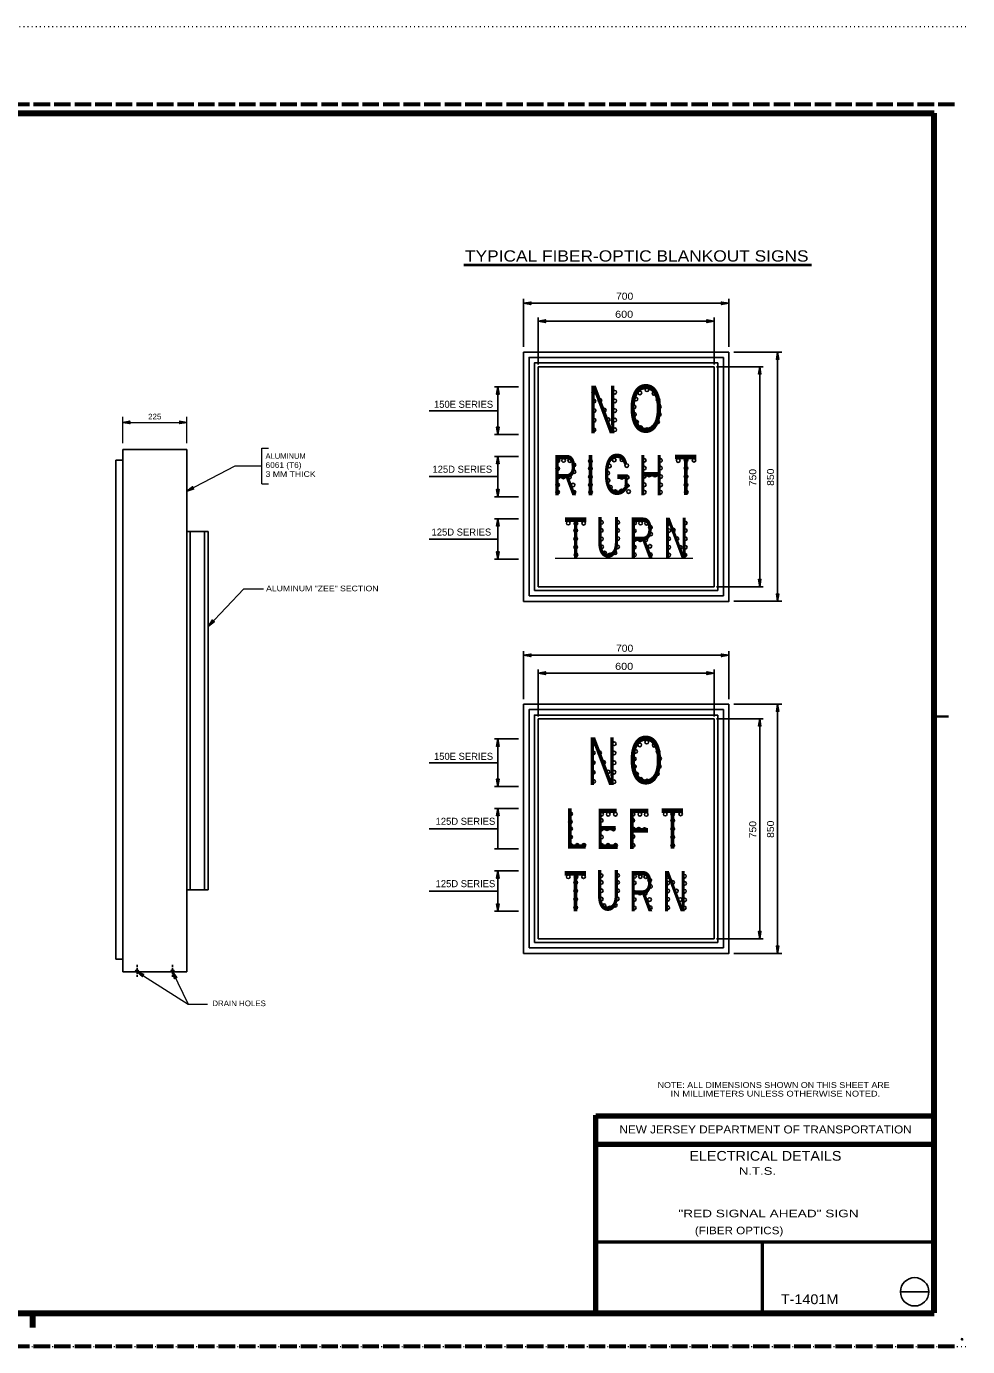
# Model space of a CAD drawing. Extents: x 312583 to 312854, y 144419 to 144597.
# Drawn here: x 312726.5 to 312853.5, y 144418.6 to 144596.8 of the extents above; entities that cross this region are included whole.
import ezdxf
from ezdxf.enums import TextEntityAlignment as Align

# ---------------------------------------------------------------- set-up
doc = ezdxf.new("R2010")
doc.units = 0
doc.header["$LTSCALE"] = 0.37
doc.header["$PDMODE"] = 32
doc.header["$PDSIZE"] = 0.185
doc.linetypes.add('DOTTED', pattern=[1.5, 0.3, -1.2])
doc.linetypes.add('LONG_DASHED', pattern=[7.5, 6, -1.5])
for name, color, linetype, lineweight in [('1', 7, 'Continuous', 25), ('10', 7, 'Continuous', 25), ('2', 7, 'Continuous', 25), ('62', 7, 'DOTTED', 13), ('63', 7, 'LONG_DASHED', 60)]:
    doc.layers.add(name, color=color, linetype=linetype, lineweight=lineweight)

msp = doc.modelspace()

# ---------------------------------------------------------------- linework, layer by layer
at = {"layer": '1', "lineweight": 158}
for p, q in [((312849, 144423.1446), (312849, 144585.0846)), ((312616.5, 144423.0846), (312849, 144423.0846)), ((312727.35, 144421.1646), (312727.35, 144423.0846))]:
    msp.add_line(p, q, dxfattribs=at)
at = {"layer": '1'}
for p, q in [((312793.5601, 144519.1749), (312793.5601, 144552.8349)), ((312793.5601, 144552.8349), (312821.2801, 144552.8349)), ((312795.5401, 144550.8549), (312819.3001, 144550.8549)), ((312795.5401, 144521.1549), (312795.5401, 144550.8549)), ((312819.3001, 144521.1549), (312819.3001, 144550.8549)), ((312819.7911, 144520.6638), (312819.7911, 144551.3538)), ((312820.5356, 144519.9194), (312820.5356, 144552.0983)), ((312738.5204, 144470.8853), (312738.5204, 144538.2293)), ((312738.5204, 144538.2293), (312739.4788, 144538.2293)), ((312739.4788, 144469.191), (312739.4788, 144539.663)), ((312739.4788, 144539.663), (312748.1038, 144539.663)), ((312748.1038, 144469.191), (312748.1038, 144539.663)), ((312748.1038, 144528.623), (312750.9788, 144528.623)), ((312748.5868, 144480.231), (312748.5868, 144528.623)), ((312750.5034, 144480.231), (312750.5034, 144528.623)), ((312750.9788, 144480.231), (312750.9788, 144528.623)), ((312795.0411, 144520.6638), (312819.7911, 144520.6638)), ((312795.5401, 144521.1549), (312819.3001, 144521.1549)), ((312794.3046, 144519.9194), (312820.5356, 144519.9194)), ((312793.5601, 144471.6549), (312793.5601, 144505.3149)), ((312793.5601, 144505.3149), (312821.2801, 144505.3149)), ((312820.5356, 144472.3994), (312820.5356, 144504.5783)), ((312795.5401, 144503.3349), (312819.3001, 144503.3349)), ((312795.5401, 144473.6349), (312795.5401, 144503.3349)), ((312819.3001, 144473.6349), (312819.3001, 144503.3349)), ((312819.7911, 144473.1438), (312819.7911, 144503.8338)), ((312748.1038, 144480.231), (312750.9788, 144480.231)), ((312794.3046, 144472.3994), (312820.5356, 144472.3994)), ((312795.0411, 144473.1438), (312819.7911, 144473.1438)), ((312795.5401, 144473.6349), (312819.3001, 144473.6349)), ((312738.5204, 144470.8853), (312739.4788, 144470.8853)), ((312739.4788, 144469.191), (312748.1038, 144469.191)), ((312741.3954, 144469.8426), (312741.3954, 144470.1033)), ((312741.3954, 144468.8613), (312741.3954, 144469.7276)), ((312741.3954, 144468.501), (312741.3954, 144468.7233)), ((312746.1871, 144469.8426), (312746.1871, 144470.1033)), ((312746.1871, 144468.8613), (312746.1871, 144469.7276)), ((312746.1871, 144468.501), (312746.1871, 144468.7233))]:
    msp.add_line(p, q, dxfattribs=at)
at = {"layer": '1', "lineweight": 13}
msp.add_line((312797.8448, 144525.0278), (312816.4093, 144525.0278), dxfattribs=at)
at = {"layer": '1', "lineweight": 35}
msp.add_line((312849, 144503.6216), (312850.932, 144503.6216), dxfattribs=at)
at = {"layer": '1', "lineweight": 80}
for p, q in [((312803.31, 144423.1446), (312803.31, 144449.8146)), ((312803.31, 144449.7246), (312849, 144449.7246)), ((312803.31, 144445.9146), (312849, 144445.9146))]:
    msp.add_line(p, q, dxfattribs=at)
at = {"layer": '1', "lineweight": 53}
for p, q in [((312849, 144432.6666), (312803.115, 144432.6666)), ((312825.7546, 144432.6666), (312825.7546, 144423.1446))]:
    msp.add_line(p, q, dxfattribs=at)
at = {"layer": '1', "lineweight": 158}
msp.add_lwpolyline([(312616.5, 144423.1446), (312616.5, 144585.0846), (312849, 144585.0846)], dxfattribs=at)
at = {"layer": '1'}
for points in [[(312793.5601, 144519.1749), (312821.2801, 144519.1749), (312821.2801, 144552.8349)], [(312794.3046, 144519.9194), (312794.3046, 144552.0983), (312820.5356, 144552.0983)], [(312795.0411, 144520.6638), (312795.0411, 144551.3538), (312819.7911, 144551.3538)], [(312793.5601, 144471.6549), (312821.2801, 144471.6549), (312821.2801, 144505.3149)], [(312794.3046, 144472.3994), (312794.3046, 144504.5783), (312820.5356, 144504.5783)], [(312795.0411, 144473.1438), (312795.0411, 144503.8338), (312819.7911, 144503.8338)]]:
    msp.add_lwpolyline(points, dxfattribs=at)
for centre in [(312803.0483, 144547.384), (312805.8787, 144547.4048), (312809.2635, 144547.3068), (312810.2159, 144547.7315), (312811.1723, 144547.2355), (312803.0721, 144546.2109), (312803.0879, 144544.9258), (312803.868, 144546.295), (312804.4601, 144544.9971), (312805.8708, 144546.2396), (312805.8708, 144544.9387), (312808.4824, 144545.4317), (312808.725, 144546.4861), (312811.7227, 144546.399), (312811.895, 144545.4515), (312803.08, 144543.6171), (312805.0105, 144543.7002), (312805.8708, 144543.6378), (312808.526, 144544.4001), (312808.8121, 144543.3775), (312811.6514, 144543.4012), (312811.89, 144544.412), (312803.0562, 144542.3251), (312805.8708, 144542.338), (312809.3507, 144542.632), (312810.2001, 144542.3499), (312811.0535, 144542.6637), (312798.2142, 144538.1701), (312798.9606, 144538.1938), (312799.7972, 144538.1691), (312802.588, 144538.1226), (312805.8094, 144538.2542), (312806.842, 144538.2918), (312809.8536, 144538.2077), (312812.0474, 144538.1998), (312814.4403, 144538.1839), (312815.5134, 144538.2156), (312816.5707, 144538.2077), (312798.1825, 144537.1088), (312800.3585, 144537.5998), (312800.3585, 144536.6653), (312802.588, 144537.1326), (312802.588, 144536.0079), (312804.9273, 144536.493), (312805.1491, 144537.4454), (312807.4984, 144537.5038), (312809.8457, 144537.1702), (312809.8615, 144536.0693), (312810.5139, 144536.2336), (312811.296, 144536.2257), (312812.0474, 144537.1623), (312812.0553, 144536.0297), (312815.5134, 144537.1543), (312815.5134, 144536.0297), (312798.1587, 144534.8991), (312798.1983, 144535.9525), (312798.9378, 144535.9624), (312799.7566, 144535.9505), (312800.2565, 144534.8833), (312802.588, 144534.8833), (312804.9808, 144535.4941), (312805.2837, 144534.5813), (312806.841, 144535.9248), (312807.5103, 144534.7991), (312807.5736, 144535.9158), (312809.8694, 144534.913), (312812.0553, 144534.9051), (312815.5134, 144534.9051), (312798.1666, 144533.925), (312800.3585, 144533.9091), (312802.6038, 144533.9091), (312805.9342, 144533.9883), (312806.7668, 144534.0556), (312807.7399, 144533.9913), (312809.8694, 144533.9151), (312812.0395, 144533.8992), (312815.5293, 144533.9309), (312799.5952, 144529.7323), (312800.6288, 144529.7085), (312801.6782, 144529.7165), (312804.0799, 144529.8254), (312806.2886, 144529.8412), (312808.5616, 144529.7501), (312809.3635, 144529.7422), (312810.1684, 144529.7175), (312810.6901, 144529.1482), (312813.2057, 144529.7145), (312815.4015, 144529.7531), (312800.6208, 144528.7423), (312800.6208, 144527.6177), (312804.0482, 144528.7562), (312804.0799, 144527.6157), (312806.2728, 144528.7482), (312806.2886, 144527.6474), (312808.4983, 144528.6888), (312808.5537, 144527.5246), (312809.3249, 144527.487), (312810.0645, 144527.4989), (312810.706, 144528.2612), (312813.1503, 144527.6236), (312813.1582, 144528.7403), (312813.768, 144528.7888), (312814.2561, 144527.6266), (312815.3936, 144528.7314), (312815.4015, 144527.6226), (312800.6208, 144526.493), (312800.6446, 144525.4713), (312804.1116, 144526.5227), (312804.5106, 144525.6961), (312805.2342, 144525.4466), (312805.8946, 144525.7278), (312806.249, 144526.5227), (312808.522, 144526.495), (312808.53, 144525.4733), (312810.6278, 144526.6059), (312810.6901, 144525.4654), (312813.1582, 144525.4377), (312813.1661, 144526.4831), (312814.7105, 144526.4495), (312815.3382, 144525.4367), (312815.4015, 144526.4901), (312802.977, 144498.7305), (312803.0325, 144499.9511), (312803.8205, 144498.7354), (312805.7916, 144498.7116), (312805.7995, 144499.9482), (312808.6933, 144498.9265), (312809.2556, 144499.7947), (312810.2001, 144500.1798), (312811.2039, 144499.7472), (312811.7306, 144498.9106), (312802.985, 144497.4058), (312804.3729, 144497.4454), (312805.7837, 144497.3949), (312808.5062, 144497.9196), (312808.526, 144496.8801), (312811.89, 144496.8999), (312811.9266, 144497.9632), (312802.977, 144496.0971), (312804.9471, 144496.1565), (312805.7758, 144496.1178), (312808.8121, 144495.8575), (312809.3982, 144495.1358), (312811.101, 144495.2229), (312811.6356, 144495.8971), (312803.0087, 144494.8764), (312805.7679, 144494.818), (312810.2318, 144494.917), (312799.912, 144490.4897), (312804.0888, 144490.4511), (312804.9897, 144490.4352), (312805.9589, 144490.4422), (312808.3498, 144490.4669), (312809.2665, 144490.4352), (312810.1248, 144490.4184), (312812.68, 144490.4659), (312813.6898, 144490.458), (312814.7709, 144490.4739), (312799.8962, 144489.4284), (312799.912, 144488.4939), (312804.0611, 144489.6007), (312804.069, 144488.4602), (312804.8343, 144488.479), (312805.7005, 144488.4622), (312808.3062, 144489.6007), (312808.3696, 144488.4444), (312809.1071, 144488.4107), (312809.911, 144488.378), (312813.7057, 144489.6185), (312813.7057, 144488.4939), (312799.912, 144487.3692), (312799.9358, 144486.2446), (312800.8198, 144486.2376), (312801.7039, 144486.2604), (312804.069, 144487.3514), (312804.1007, 144486.2347), (312804.9778, 144486.2268), (312805.9787, 144486.2258), (312808.3379, 144487.4227), (312808.3458, 144486.2426), (312813.7057, 144487.3692), (312813.7057, 144486.2446), (312799.5952, 144481.9985), (312800.6208, 144481.2223), (312800.6525, 144481.9905), (312801.6623, 144482.0143), (312804.0324, 144482.1549), (312804.0482, 144481.2362), (312806.249, 144482.1786), (312806.249, 144481.2362), (312808.4983, 144481.1688), (312808.53, 144482.04), (312809.3239, 144482.0163), (312810.0575, 144482.0153), (312810.603, 144481.5252), (312813.0394, 144481.1728), (312813.079, 144482.044), (312813.6809, 144481.2292), (312815.2748, 144482.0668), (312815.2986, 144481.1005), (312800.6208, 144480.0977), (312800.6208, 144478.973), (312804.0482, 144480.1115), (312804.0482, 144478.9869), (312806.2252, 144479.0106), (312806.2569, 144480.1194), (312808.5141, 144479.8937), (312809.2774, 144479.7927), (312810.0011, 144479.7809), (312810.6901, 144480.6936), (312813.0394, 144480.0957), (312814.2007, 144480.0828), (312815.2827, 144480.0472), (312800.6208, 144477.8484), (312804.4393, 144478.081), (312805.1946, 144477.784), (312805.9342, 144478.1523), (312808.4983, 144478.9196), (312808.4983, 144477.7949), (312810.5723, 144478.9196), (312810.6585, 144477.8108), (312813.0315, 144478.9631), (312813.0315, 144477.8306), (312814.7105, 144478.9295), (312815.259, 144477.7979), (312815.2907, 144478.8829)]:
    msp.add_circle(centre, 0.2475, dxfattribs=at)
for centre in [(312741.3983, 144469.189), (312746.19, 144469.189)]:
    msp.add_arc(centre, 0.2396, 0, 180, dxfattribs=at)
msp.add_point((312852.75, 144419.5846), dxfattribs=at)
at = {"layer": '10'}
msp.add_line((312844.4384, 144425.9659), (312848.2794, 144425.9659), dxfattribs=at)
msp.add_circle((312846.3494, 144425.9805), 1.9159, dxfattribs=at)
at = {"layer": '2', "lineweight": 40}
msp.add_line((312785.4989, 144564.5869), (312832.4133, 144564.5869), dxfattribs=at)
at = {"layer": '2'}
for p, q in [((312793.5601, 144553.516), (312793.5601, 144559.9946)), ((312821.2801, 144559.4164), (312793.5601, 144559.4164)), ((312821.2801, 144553.516), (312821.2801, 144559.9946)), ((312795.5401, 144551.1558), (312795.5401, 144557.4839)), ((312819.3001, 144557.0008), (312795.5401, 144557.0008)), ((312819.3001, 144551.1558), (312819.3001, 144557.4839)), ((312821.9612, 144552.8349), (312828.4319, 144552.8349)), ((312827.8537, 144519.1828), (312827.8537, 144552.8349)), ((312819.6011, 144550.8549), (312825.9212, 144550.8549)), ((312825.446, 144521.1549), (312825.446, 144550.8549)), ((312789.6555, 144548.1225), (312792.8711, 144548.1225)), ((312790.0911, 144541.6994), (312790.0911, 144548.1225)), ((312790.0911, 144544.907), (312780.8327, 144544.907)), ((312789.6555, 144541.6994), (312792.8711, 144541.6994)), ((312789.6555, 144538.7452), (312792.8711, 144538.7452)), ((312790.0911, 144533.2804), (312790.0911, 144538.7452)), ((312790.0911, 144536.0128), (312780.8327, 144536.0128)), ((312807.6102, 144534.7773), (312807.8953, 144534.7773)), ((312789.6555, 144533.2804), (312792.8711, 144533.2804)), ((312789.6555, 144530.3262), (312792.8711, 144530.3262)), ((312790.0911, 144524.8694), (312790.0911, 144530.3262)), ((312790.0911, 144527.5938), (312780.8327, 144527.5938)), ((312789.6555, 144524.8694), (312792.8711, 144524.8694)), ((312819.6011, 144521.1549), (312825.9212, 144521.1549)), ((312821.9612, 144519.1828), (312828.4319, 144519.1828)), ((312793.5601, 144505.996), (312793.5601, 144512.4746)), ((312821.2801, 144511.8964), (312793.5601, 144511.8964)), ((312821.2801, 144505.996), (312821.2801, 144512.4746)), ((312795.5401, 144503.6358), (312795.5401, 144509.9639)), ((312819.3001, 144503.6358), (312819.3001, 144509.9639)), ((312819.3001, 144509.4808), (312795.5401, 144509.4808)), ((312821.9612, 144505.3149), (312828.4319, 144505.3149)), ((312827.8537, 144471.6628), (312827.8537, 144505.3149)), ((312819.6011, 144503.3349), (312825.9212, 144503.3349)), ((312825.446, 144473.6349), (312825.446, 144503.3349)), ((312789.6555, 144500.6025), (312792.8711, 144500.6025)), ((312790.0911, 144497.387), (312780.8327, 144497.387)), ((312789.6555, 144494.1794), (312792.8711, 144494.1794)), ((312789.6555, 144491.2252), (312792.8711, 144491.2252)), ((312790.0911, 144485.7604), (312790.0911, 144491.2252)), ((312790.0911, 144488.4928), (312780.8327, 144488.4928)), ((312789.6555, 144485.7604), (312792.8711, 144485.7604)), ((312789.6555, 144482.8062), (312792.8711, 144482.8062)), ((312790.0911, 144477.3494), (312790.0911, 144482.8062)), ((312790.0911, 144480.0738), (312780.8327, 144480.0738)), ((312789.6555, 144477.3494), (312792.8711, 144477.3494)), ((312819.6011, 144473.6349), (312825.9212, 144473.6349)), ((312821.9612, 144471.6628), (312828.4319, 144471.6628))]:
    msp.add_line(p, q, dxfattribs=at)
at = {"layer": '2', "lineweight": 13}
for p, q in [((312739.4788, 144540.514), (312739.4788, 144544.079)), ((312748.1038, 144540.514), (312748.1038, 144544.079)), ((312739.4788, 144543.3276), (312748.1038, 144543.3276)), ((312758.2391, 144537.4473), (312754.6128, 144537.4473)), ((312758.2391, 144535.0476), (312759.1284, 144535.0476)), ((312751.0554, 144515.8503), (312755.8011, 144520.8873)), ((312755.8011, 144520.8873), (312758.4538, 144520.8873)), ((312741.3954, 144469.191), (312748.2801, 144464.8056)), ((312746.1871, 144469.191), (312748.2801, 144464.8056)), ((312748.2801, 144464.8056), (312750.9251, 144464.8056))]:
    msp.add_line(p, q, dxfattribs=at)
at = {"layer": '2'}
for points in [[(312793.5601, 144559.4164), (312794.558, 144559.2501), (312794.2254, 144559.4164), (312794.558, 144559.5827)], [(312821.2801, 144559.4164), (312820.2822, 144559.5827), (312820.6148, 144559.4164), (312820.2822, 144559.2501)], [(312795.5401, 144557.0008), (312796.538, 144556.8345), (312796.2054, 144557.0008), (312796.538, 144557.1671)], [(312819.3001, 144557.0008), (312818.3022, 144557.1671), (312818.6348, 144557.0008), (312818.3022, 144556.8345)], [(312827.8537, 144552.8349), (312827.6874, 144551.837), (312827.8537, 144552.1696), (312828.02, 144551.837)], [(312825.446, 144550.8549), (312825.2797, 144549.857), (312825.446, 144550.1896), (312825.6123, 144549.857)], [(312790.0911, 144548.1225), (312789.9327, 144547.1246), (312790.0911, 144547.4572), (312790.2654, 144547.1246)], [(312739.4788, 144543.3276), (312740.4448, 144543.1666), (312740.1228, 144543.3276), (312740.4448, 144543.4886)], [(312748.1038, 144543.3276), (312747.1378, 144543.4886), (312747.4598, 144543.3276), (312747.1378, 144543.1666)], [(312790.0911, 144541.6994), (312790.2654, 144542.6973), (312790.0911, 144542.3646), (312789.9327, 144542.6973)], [(312790.0911, 144538.7452), (312789.9327, 144537.7473), (312790.0911, 144538.0799), (312790.2654, 144537.7473)], [(312748.1038, 144534.0663), (312749.0391, 144534.3653), (312748.6788, 144534.3653), (312748.8934, 144534.6566)], [(312790.0911, 144533.2804), (312790.2654, 144534.2783), (312790.0911, 144533.9457), (312789.9327, 144534.2783)], [(312790.0911, 144530.3262), (312789.9327, 144529.3283), (312790.0911, 144529.661), (312790.2654, 144529.3283)], [(312790.0911, 144524.8694), (312790.2654, 144525.8673), (312790.0911, 144525.5346), (312789.9327, 144525.8673)], [(312825.446, 144521.1549), (312825.6123, 144522.1528), (312825.446, 144521.8202), (312825.2797, 144522.1528)], [(312827.8537, 144519.1828), (312828.02, 144520.1807), (312827.8537, 144519.8481), (312827.6874, 144520.1807)], [(312751.0554, 144515.8503), (312751.8298, 144516.4406), (312751.4924, 144516.318), (312751.5998, 144516.663)], [(312793.5601, 144511.8964), (312794.558, 144511.7301), (312794.2254, 144511.8964), (312794.558, 144512.0627)], [(312821.2801, 144511.8964), (312820.2822, 144512.0627), (312820.6148, 144511.8964), (312820.2822, 144511.7301)], [(312795.5401, 144509.4808), (312796.538, 144509.3145), (312796.2054, 144509.4808), (312796.538, 144509.6471)], [(312819.3001, 144509.4808), (312818.3022, 144509.6471), (312818.6348, 144509.4808), (312818.3022, 144509.3145)], [(312827.8537, 144505.3149), (312827.6874, 144504.317), (312827.8537, 144504.6496), (312828.02, 144504.317)], [(312825.446, 144503.3349), (312825.2797, 144502.337), (312825.446, 144502.6696), (312825.6123, 144502.337)], [(312790.0911, 144494.1794), (312790.2654, 144495.1773), (312790.0911, 144494.8446), (312789.9327, 144495.1773)], [(312790.0911, 144491.2252), (312789.9327, 144490.2273), (312790.0911, 144490.5599), (312790.2654, 144490.2273)], [(312790.0911, 144482.8062), (312789.9327, 144481.8083), (312790.0911, 144482.141), (312790.2654, 144481.8083)], [(312790.0911, 144477.3494), (312790.2654, 144478.3473), (312790.0911, 144478.0146), (312789.9327, 144478.3473)], [(312825.446, 144473.6349), (312825.6123, 144474.6328), (312825.446, 144474.3002), (312825.2797, 144474.6328)], [(312827.8537, 144471.6628), (312828.02, 144472.6607), (312827.8537, 144472.3281), (312827.6874, 144472.6607)], [(312741.3954, 144469.191), (312742.1238, 144468.5316), (312741.9398, 144468.846), (312742.3001, 144468.8076)], [(312746.1871, 144469.191), (312746.4631, 144468.248), (312746.4708, 144468.6083), (312746.7544, 144468.386)]]:
    msp.add_lwpolyline(points, close=True, dxfattribs=at)
at = {"layer": '2', "lineweight": 13}
for points in [[(312758.2391, 144535.0476), (312758.2391, 144539.8393), (312759.1284, 144539.8393)], [(312758.2391, 144537.4473), (312754.6128, 144537.4473), (312748.1038, 144534.0663)]]:
    msp.add_lwpolyline(points, dxfattribs=at)
at = {"layer": '2'}
msp.add_lwpolyline([(312790.0911, 144494.1794), (312790.0911, 144500.6025), (312789.9327, 144499.6046), (312790.0911, 144499.9372), (312790.2654, 144499.6046), (312790.0911, 144500.6025)], dxfattribs=at)
at = {"layer": '62'}
for p, q in [((312601.2, 144596.7846), (312853.5, 144596.7846)), ((312601.2, 144418.5846), (312853.5, 144418.5846))]:
    msp.add_line(p, q, dxfattribs=at)
at = {"layer": '63'}
for p, q in [((312851.75, 144586.2246), (312583.526, 144586.2246)), ((312851.75, 144418.5846), (312583.526, 144418.5846))]:
    msp.add_line(p, q, dxfattribs=at)

# ---------------------------------------------------------------- texts
at = {"layer": '1'}
for s, height, width, p in [('N', 6.431, 0.65, (312804.273, 144541.8578)), ('O', 6.431, 0.7, (312810.065, 144541.9924)), ('R', 5.441, 0.65, (312799.1622, 144533.5101)), ('I', 5.441, 0.75, (312802.6053, 144533.4863)), ('G', 5.441, 0.65, (312806.138, 144533.6051)), ('H', 5.441, 0.65, (312810.7655, 144533.4942)), ('T', 5.441, 0.7, (312815.467, 144533.518)), ('T', 5.441, 0.7, (312800.5933, 144525.0594)), ('U', 5.441, 0.65, (312804.9914, 144525.1386)), ('R', 5.441, 0.65, (312809.49, 144525.0594)), ('N', 5.441, 0.65, (312814.1039, 144525.0198)), ('N', 6.431, 0.65, (312804.1859, 144494.3774)), ('O', 6.431, 0.7, (312810.0728, 144494.5358)), ('L', 5.441, 0.75, (312800.6341, 144485.7762)), ('E', 5.441, 0.65, (312804.8763, 144485.7683)), ('F', 5.441, 0.7, (312809.0707, 144485.7683)), ('T', 5.441, 0.7, (312813.6613, 144485.7921)), ('U', 5.441, 0.65, (312804.9598, 144477.4682)), ('R', 5.441, 0.65, (312809.4583, 144477.3414)), ('N', 5.441, 0.65, (312813.977, 144477.3494)), ('T', 5.441, 0.7, (312800.5695, 144477.3335)), ('NEW JERSEY DEPARTMENT OF TRANSPORTATION', 1.08, 1.1, (312826.2285, 144447.3546)), ('ELECTRICAL DETAILS', 1.315, 1.1, (312826.2107, 144443.6759)), ('T-1401M', 1.319, 1.1, (312832.1762, 144424.3176))]:
    msp.add_text(s, height=height, dxfattribs=dict(at, width=width)).set_placement(p, align=Align.CENTER)
for s, width, p in [('NOTE: ALL DIMENSIONS SHOWN ON THIS SHEET ARE', 1.15, (312811.6611, 144453.5054)), ('     IN MILLIMETERS UNLESS OTHERWISE NOTED.', 1.2, (312811.661, 144452.3354))]:
    msp.add_text(s, height=0.78, dxfattribs=dict(at, width=width)).set_placement(p)
at = {"layer": '2'}
for s, height, width, p in [('TYPICAL FIBER-OPTIC BLANKOUT SIGNS', 1.52, 1.15, (312808.847, 144565.0394)), ('700', 0.9504, 1.1, (312807.2075, 144559.8916)), ('600', 0.9504, 1.15, (312807.1442, 144557.4522)), ('700', 0.9504, 1.1, (312807.2075, 144512.3716)), ('600', 0.9504, 1.15, (312807.1442, 144509.9322)), ('    N.T.S.  ', 1.02, 1.3, (312824.6461, 144441.778)), ('           "RED SIGNAL AHEAD" SIGN          ', 1.02, 1.35, (312826.3718, 144436.0399)), ('               (FIBER OPTICS)               ', 1.02, 1.15, (312822.6572, 144433.7476))]:
    msp.add_text(s, height=height, dxfattribs=dict(at, width=width)).set_placement(p, align=Align.CENTER)
for s, height, p in [('150E SERIES', 0.9504, (312781.4742, 144545.303)), ('ALUMINUM', 0.76, (312758.7433, 144538.4162)), ('125D SERIES', 0.9504, (312781.2707, 144536.5355)), ('125D SERIES', 0.9504, (312781.1493, 144528.0558)), ('150E SERIES', 0.9504, (312781.4742, 144497.783)), ('125D SERIES', 0.9504, (312781.6959, 144489.0155)), ('125D SERIES', 0.9504, (312781.6959, 144480.5966))]:
    msp.add_text(s, height=height, dxfattribs=at).set_placement(p)
for s, width, p in [('225', 1.05, (312742.8936, 144543.7368)), ('3 MM THICK', 1.15, (312758.7433, 144535.9762)), ('6061 (T6)', 1.1, (312758.7433, 144537.1962)), ('ALUMINUM "ZEE" SECTION', 1.15, (312758.8141, 144520.5413)), ('DRAIN HOLES', 1.05, (312751.5538, 144464.5363))]:
    msp.add_text(s, height=0.76, dxfattribs=dict(at, width=width)).set_placement(p)
at = {"layer": '2', "width": 1.1}
for s, p in [('750', (312824.9708, 144535.8851)), ('850', (312827.3785, 144535.935)), ('750', (312824.9708, 144488.3651)), ('850', (312827.3785, 144488.415))]:
    msp.add_text(s, height=0.9504, rotation=90, dxfattribs=at).set_placement(p, align=Align.CENTER)

doc.saveas('drawing.dxf')
